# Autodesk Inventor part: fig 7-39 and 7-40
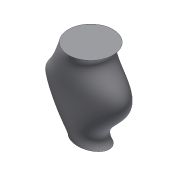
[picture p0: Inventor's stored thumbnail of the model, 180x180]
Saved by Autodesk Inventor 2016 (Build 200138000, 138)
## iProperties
Shininess: 64.0
Length Units: 11269
Angle Units: 11279
Time Units: 11290
Mass Units: 11283
Length Display Precision: 3
Angle Display Precision: 2
Compacted: True
Part Number: fig 7-39 and 7-40
Document SubType Name: Modeling
Created: 2002-12
Designer: deepak
Density: 1 g/cm^3
Material: Generic
Appearance: Default
Density: 0.0
Volumn: 0.0
Area: 0.0
PropertySet Name: Model Information
Control State: 0
Master: False
Checked Out: False
Author: deepak
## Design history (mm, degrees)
sketch "Sketch1"
  geometry: 2 further points; 1 other entity
  constraints: 1 coincident, 3 other
workplane "Work Plane1"
workplane "Work Plane2"
sketch "Sketch3"
  geometry: C1 r 60 at (0, 0); 1 further point
  constraints: 1 centre point, 1 coincident, 1 other
sketch "Sketch4"
  geometry: 8 further points
  constraints: 8 other
sketch "Sketch5"
  geometry: 6 further points
  constraints: 6 other
sketch "Sketch6"
  geometry: 6 further points
  constraints: 6 other
  dimensions: "d20" = 35 distance of point (0, 0) point (-35, 0); "d21" = 0 vertical distance of point (0, 0) point (-35, 0); "d22" = 225 vertical distance of point (0, 0) point (-60, 225); "d23" = 60 horizontal distance of point (0, 0) point (-60, 225); "d24" = 100 horizontal distance of point (0, 0) point (-100, 125); "d25" = 125 vertical distance of point (0, 0) point (-100, 125)
loft "Loft3" dims "d42" = 0, "d43" = 90 deg, "d44" = 0, "d45" = 90 deg, "d46" = 0, "d47" = 90 deg, "d48" = 0, "d49" = 90 deg
node "Sketch7"
sketch "Sketch8"
  geometry: 1 further point
body "Solid1"
other parameters: "d5" = 125
